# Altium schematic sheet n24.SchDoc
size A3
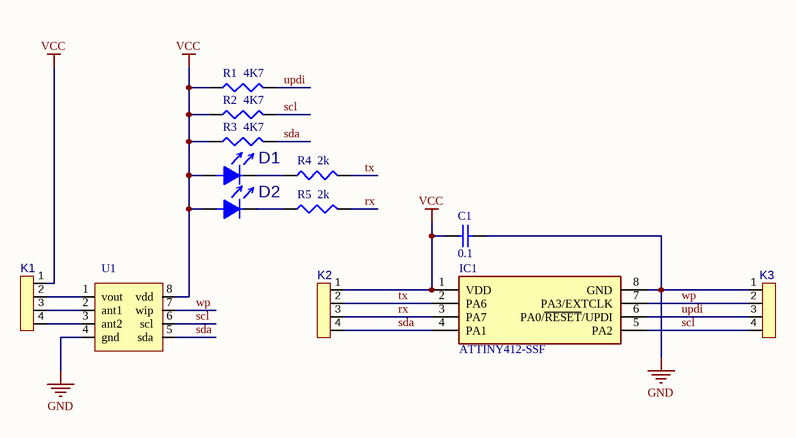
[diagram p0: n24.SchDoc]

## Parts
C1  value 0.1  [SM0805]  (hidden comment: cap0805)
D1  LIGHT_SM0805  [SM0805_diode]  (value not drawn)
D2  LIGHT_SM0805  [SM0805_diode]  (value not drawn)
IC1  ATTINY412-SSF  [SOIC127P600X175-8N]
K1  1x4PLS  [4_PLS_2.54]  (value not drawn)
K2  1x4PLS  [4_PLS_2.54]  (value not drawn)
K3  1x4PLS  [4_PLS_2.54]  (value not drawn)
R1  value 4K7  [SM0805]  (hidden comment: res0805)
R2  value 4K7  [SM0805]  (hidden comment: res0805)
R3  value 4K7  [SM0805]  (hidden comment: res0805)
R4  value 2k  [SM0805]  (hidden comment: res0805)
R5  value 2k  [SM0805]  (hidden comment: res0805)
U1  n24rf04  [SO8_L]  (value not drawn)

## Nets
GND: C1.2 IC1.8(GND) K3.1 U1.4(gnd)
VCC: C1.1 D1.1(a) D2.1(a) IC1.1(VDD) K1.1 K2.1 R1.1 R2.1 R3.1 U1.8(vdd)
rx: IC1.3(PA7) K2.3 R5.2
scl: IC1.5(PA2) K3.4 R2.2 U1.6(scl)
sda: IC1.4(PA1) K2.4 R3.2 U1.5(sda)
tx: IC1.2(PA6) K2.2 R4.2
updi: IC1.6(PA0/~{RESET}/UPDI) K3.3 R1.2
wp: IC1.7(PA3/EXTCLK) K3.2 U1.7(wip)
NetD1_2: D1.2(k) R4.1
NetD2_2: D2.2(k) R5.1
NetK1_2: K1.2 U1.1(vout)
NetK1_3: K1.3 U1.2(ant1)
NetK1_4: K1.4 U1.3(ant2)

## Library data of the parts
C1 = cap0805: Capacitor
IC1 = ATTINY412-SSF: Integrated Circuit; Manufacturer_Name: Microchip
K1-K3 = 1x4PLS: 1 row 4 pin 2.54mm
R1-R5 = res0805: Resistor
U1 = n24rf04: eeprom & nfc tag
